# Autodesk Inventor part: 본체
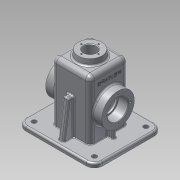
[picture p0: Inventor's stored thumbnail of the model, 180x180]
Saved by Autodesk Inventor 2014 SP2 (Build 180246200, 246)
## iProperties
Created: 2016-08
Part Number: 본체
Material: 알루미늄 6061
Document SubType Name: Modeling
Designer: user
Density: 2.71 g/cm^3
Appearance: 알루미늄 - 평지
Mass: 800.192 g
Surface Area: 912.049 cm^2
Volume: 295.274 cm^3
Author: user
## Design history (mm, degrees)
sketch "스케치1"
  geometry: L1 (-65, -57.5)-(65, -57.5); L2 (65, -57.5)-(65, 57.5); L3 (65, 57.5)-(-65, 57.5); L4 (-65, 57.5)-(-65, -57.5); L5 (-65, -57.5)-(65, 57.5); L6 (65, -57.5)-(-65, 57.5); 1 further point
  constraints: 12 end point, 2 midpoint, 2 parallel, 1 horizontal, 1 perpendicular
  dimensions: "d0" = 130 distance of L2.end L3.end; "d1" = 115 distance of L1.end L2.end
extrude "돌출1" new body sketch "스케치1" distance "d2" = 10; taper "d3" = 0 deg
sketch "스케치2"
  geometry: L1 (65, -57.5)-(-65, -57.5) reference; L2 (65, 57.5)-(65, -57.5) reference; L3 (-65, 57.5)-(65, 57.5) reference; L4 (-65, -57.5)-(-65, 57.5) reference; L5 (-60, 52.5)-(60, 52.5); L6 (60, 52.5)-(60, -52.5); L7 (60, -52.5)-(-60, -52.5); L8 (-60, -52.5)-(-60, 52.5); 1 further point
  constraints: 8 end point, 3 other
  dimensions: "d4" = 5 distance between parallel lines of L4 L8
extrude "돌출2" cut sketch "스케치2" distance "d5" = 3; taper "d6" = 0 deg
sketch "스케치3"
  geometry: L1 (32.5, 110)-(-32.5, 110); L2 (-32.5, 110)-(-32.5, 0); L3 (-32.5, 0)-(32.5, 0); L4 (32.5, 0)-(32.5, 110); 2 further points
  constraints: 8 end point, 2 parallel, 1 coincident, 1 horizontal, 1 midpoint, 1 perpendicular
  dimensions: "d7" = 65 distance of L2.end L3.end; "d8" = 110 distance of L1.end L2.end
extrude "돌출3" join sketch "스케치3" stored distance "d9" = 65; taper "d10" = 0 deg
sketch "스케치5"
  geometry: C1 r 27.5 at (-45, 32.5); 1 further point
  constraints: 1 centre point, 1 horizontal alignment
  dimensions: "d16" = 55 distance of point (10, 32.5) C1.centre; "d17" = 55 diameter of C1
extrude "돌출5" join sketch "스케치5" distance "d18" = 15; taper "d20" = 0 deg; dims "d19" = 80, "d21" = 0
sketch "스케치4"
  geometry: L1 (27.5, 105)-(-27.5, 105); L2 (-27.5, 105)-(-27.5, 0); L3 (-27.5, 0)-(27.5, 0); L4 (27.5, 0)-(27.5, 105); L5 (32.5, 110)-(-32.5, 110) reference; 2 further points
  constraints: 8 end point, 2 parallel, 1 coincident, 1 horizontal, 1 midpoint, 1 perpendicular
  dimensions: "d11" = 55 distance of L2.end L3.end; "d13" = 5 distance between parallel lines of L5 L1
extrude "돌출4" cut sketch "스케치4" stored distance "d14" = 55; taper "d15" = 0 deg
node "작업 평면1"
hole "구멍1" diameter "d24" = 30; stored, may be unused: countersink angle "d28" = 90 deg, drill point angle "d30" = 0 deg; dims "d22" = 10, "d23" = 10, "d25" = 6, "d26" = 35, "d27" = 17, "d29" = 30
hole "구멍2" diameter "d33" = 30; stored, may be unused: countersink angle "d37" = 90 deg, drill point angle "d39" = 0 deg; dims "d31" = 10, "d32" = 10, "d34" = 6, "d35" = 35, "d36" = 17, "d38" = 30
sketch "스케치6"
  geometry: C1 r 20 at (32.5, -32.5); 1 further point
  constraints: 1 centre point, 1 coincident
  dimensions: "d41" = 40 diameter of C1
extrude "돌출6" join sketch "스케치6" stored distance "d42" = 15; taper "d43" = 7 deg
hole "구멍3" diameter "d46" = 21; stored, may be unused: countersink angle "d50" = 90 deg, drill point angle "d52" = 0 deg; dims "d44" = 10, "d45" = 10, "d47" = 6, "d48" = 35, "d49" = 17, "d51" = 30
fillet "모깎기1" dims "d53" = 8
fillet "모깎기13" dims "d111" = 3
fillet "모깎기2" dims "d54" = 14
sketch "스케치7"
  geometry: L1 (-42.5, 9)-(-27.5, 9); L2 (-42.5, 9)-(-42.5, 29); L3 (-42.5, 29)-(-27.5, 29); L4 (-27.5, 29)-(-27.5, 9); 1 further point
  constraints: 8 end point, 2 perpendicular, 1 parallel, 1 vertical
  dimensions: "d142" = 15 distance of L1.start L1.end; "d143" = 20 distance of L1.start L2.end; "d144" = 9 vertical distance of L1.start point (0, 0); "d145" = 27.5 horizontal distance of L3.end point (0, 0)
extrude "돌출7" join sketch "스케치7" stored distance "d57" = 6; taper "d58" = 0 deg
sketch "스케치8"
  geometry: L1 (32.5, 70)-(32.5, 10); L2 (32.5, 10)-(49.5, 10); L3 (49.5, 10)-(41.068, 70); L4 (41.068, 70)-(32.5, 70); L5 (57.5, 10)-(57.5, 3) reference; L6 (43.5, 10)-(57.5, 10) reference; 2 further points
  constraints: 8 end point, 1 coincident, 1 parallel, 1 perpendicular, 1 point on line, 1 vertical
  dimensions: "d59" = 70 vertical distance of L3.end point (0, 0); "d61" = 8 deg angle of L3 L5; "d62" = 8 horizontal distance of L5.end L2.end
extrude "돌출8" join sketch "스케치8" stored distance "d63" = 10; taper "d64" = 0 deg
hole "구멍4" diameter "d67" = 8; stored, may be unused: countersink angle "d71" = 90 deg, drill point angle "d73" = 0 deg; dims "d65" = 10, "d66" = 10, "d68" = 6, "d69" = 35, "d70" = 17, "d72" = 30
hole "구멍5" diameter "d76" = 8; stored, may be unused: countersink angle "d80" = 90 deg, drill point angle "d82" = 0 deg; dims "d74" = 10, "d75" = 10, "d77" = 6, "d78" = 35, "d79" = 17, "d81" = 30
hole "구멍6" diameter "d85" = 8; stored, may be unused: countersink angle "d89" = 90 deg, drill point angle "d91" = 0 deg; dims "d83" = 10, "d84" = 10, "d86" = 6, "d87" = 35, "d88" = 17, "d90" = 30
hole "구멍7" diameter "d94" = 8; stored, may be unused: countersink angle "d98" = 90 deg, drill point angle "d100" = 0 deg; dims "d92" = 10, "d93" = 10, "d95" = 6, "d96" = 35, "d97" = 17, "d99" = 30
fillet "모깎기3" dims "d101" = 9
fillet "모깎기5" dims "d103" = 3
fillet "모깎기6" dims "d104" = 3
fillet "모깎기8" dims "d106" = 3
fillet "모깎기9" dims "d107" = 3
fillet "모깎기10" dims "d108" = 3
sketch "스케치9"
  geometry: 2 further points
  constraints: 1 horizontal alignment
  dimensions: "d112" = 14.5 distance of point (14.5, 0) point (0, 0)
hole "구멍8" sketch "스케치9" at (14.5, 0) diameter "d113" = 2.459; stored, may be unused: countersink angle "d117" = 90 deg, drill point angle "d119" = 118 deg; dims "d114" = 7, "d115" = 35, "d116" = 17, "d118" = 9
sketch "스케치10"
  geometry: C1 r 17.5 at (0, 0) reference; 2 further points
  constraints: 1 vertical alignment
  dimensions: "d123" = 21 distance of point (0, 21) C1.centre
hole "구멍9" sketch "스케치10" at (0, 21) diameter "d124" = 3.242; stored, may be unused: countersink angle "d128" = 90 deg, drill point angle "d130" = 118 deg; dims "d125" = 8, "d126" = 35, "d127" = 17, "d129" = 10
fillet "모깎기14" dims "d134" = 0.3
fillet "모깎기15" dims "d135" = 3
fillet "모깎기16" dims "d136" = 3
sketch "스케치11"
  geometry: L1 (0, -8)-(92, -8) reference; L2 (-18, 4.5)-(-18, 44.5) reference; 2 further points
  constraints: 1 other
  dimensions: "d137" = 32.5 distance from line of L1 point (8, 24.5); "d138" = 26 distance from line of L2 point (8, 24.5)
feature "엠보싱1" sketch "스케치11" dims "d139" = 0.5, "d140" = 0
fillet "모깎기17" dims "d146" = 3
fillet "모깎기18" dims "d147" = 1
chamfer "모따기1" distance "d148" = 1; stored, may be unused: second distance "d149" = 2, angle "d150" = 45 deg
fillet "모깎기19" dims "d151" = 3
fillet "모깎기20" dims "d152" = 3
node "솔리드1"
mirror "대칭1"
mirror "대칭2"
pattern_circular "원형 패턴1" dims angle "d121" = 360 deg
pattern_circular "원형 패턴2" dims angle "d132" = 360 deg
mirror "대칭3"
node "투영된 루프1"
